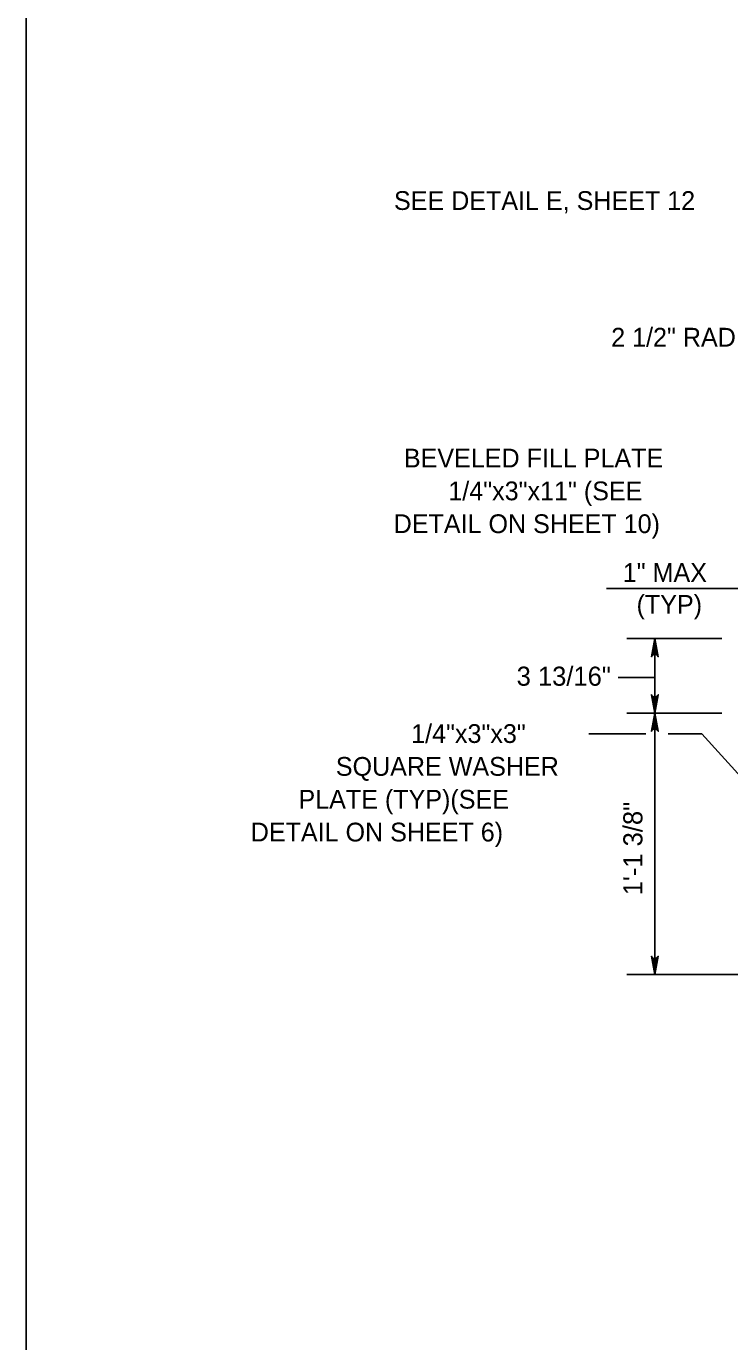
# Model space of a CAD drawing. Extents: x 632007860 to 635435983, y 295418622 to 297794622.
# Drawn here: x 634570860 to 634685141, y 297463893 to 297677572 of the extents above; entities that cross this region are included whole.
import ezdxf

# ---------------------------------------------------------------- set-up
doc = ezdxf.new("R2010")
doc.units = 0
for name, color, linetype in [('1', 7, 'Continuous'), ('S-DETL-DIMS', 7, 'Continuous'), ('S-DETL-T120', 7, 'Continuous')]:
    doc.layers.add(name, color=color, linetype=linetype)

msp = doc.modelspace()

# ---------------------------------------------------------------- linework, layer by layer
at = {"layer": '1'}
msp.add_line((634570860, 297215622), (634570860, 297779622), dxfattribs=at)
at = {"layer": 'S-DETL-DIMS'}
for p, q in [((634665111, 297586247), (634696849, 297586247)), ((634668443, 297578118), (634683847, 297578118)), ((634672972, 297578118), (634672972, 297523552)), ((634672972, 297571814), (634667041, 297571814)), ((634668443, 297566018), (634683847, 297566018)), ((634662269, 297562622), (634671501, 297562622)), ((634675127, 297562622), (634680614, 297562622)), ((634680614, 297562622), (634687563, 297555006)), ((634668443, 297523552), (634745434, 297523552))]:
    msp.add_line(p, q, dxfattribs=at)
for points in [[(634672972, 297578118), (634673527, 297575158), (634673448, 297575272), (634673369, 297575386), (634673270, 297575445), (634673171, 297575504), (634673071, 297575521), (634672972, 297575538), (634672873, 297575521), (634672774, 297575504), (634672675, 297575445), (634672575, 297575386), (634672496, 297575272), (634672417, 297575158), (634672972, 297578118), (634672496, 297575272), (634672575, 297575386), (634672972, 297578118), (634672675, 297575445), (634672774, 297575504), (634672972, 297578118), (634672873, 297575521), (634672972, 297575538), (634672972, 297578118), (634673071, 297575521), (634673171, 297575504), (634672972, 297578118), (634673270, 297575445), (634673369, 297575386), (634672972, 297578118), (634673448, 297575272)], [(634672972, 297566018), (634673527, 297568978), (634673448, 297568863), (634673369, 297568749), (634673270, 297568691), (634673171, 297568632), (634673071, 297568615), (634672972, 297568598), (634672873, 297568615), (634672774, 297568632), (634672675, 297568691), (634672575, 297568749), (634672496, 297568863), (634672417, 297568978), (634672972, 297566018), (634672496, 297568863), (634672575, 297568749), (634672972, 297566018), (634672675, 297568691), (634672774, 297568632), (634672972, 297566018), (634672873, 297568615), (634672972, 297568598), (634672972, 297566018), (634673071, 297568615), (634673171, 297568632), (634672972, 297566018), (634673270, 297568691), (634673369, 297568749), (634672972, 297566018), (634673448, 297568863)], [(634672972, 297566018), (634673527, 297563059), (634673448, 297563173), (634673369, 297563287), (634673270, 297563346), (634673171, 297563404), (634673071, 297563421), (634672972, 297563438), (634672873, 297563421), (634672774, 297563404), (634672675, 297563346), (634672575, 297563287), (634672496, 297563173), (634672417, 297563059), (634672972, 297566018), (634672496, 297563173), (634672575, 297563287), (634672972, 297566018), (634672675, 297563346), (634672774, 297563404), (634672972, 297566018), (634672873, 297563421), (634672972, 297563438), (634672972, 297566018), (634673071, 297563421), (634673171, 297563404), (634672972, 297566018), (634673270, 297563346), (634673369, 297563287), (634672972, 297566018), (634673448, 297563173)], [(634672972, 297523552), (634672417, 297526511), (634672496, 297526397), (634672575, 297526283), (634672675, 297526224), (634672774, 297526165), (634672873, 297526148), (634672972, 297526131), (634673071, 297526148), (634673171, 297526165), (634673270, 297526224), (634673369, 297526283), (634673448, 297526397), (634673527, 297526511), (634672972, 297523552), (634673448, 297526397), (634673369, 297526283), (634672972, 297523552), (634673270, 297526224), (634673171, 297526165), (634672972, 297523552), (634673071, 297526148), (634672972, 297526131), (634672972, 297523552), (634672873, 297526148), (634672774, 297526165), (634672972, 297523552), (634672675, 297526224), (634672575, 297526283), (634672972, 297523552), (634672496, 297526397)]]:
    msp.add_lwpolyline(points, dxfattribs=at)

# ---------------------------------------------------------------- texts
at = {"layer": 'S-DETL-T120'}
for s, height, p in [('SEE DETAIL E, SHEET 12', 3048.01, (634630598, 297647742)), ('2 1/2" RADIUS', 3048.01, (634665890, 297625543)), ('BEVELED FILL PLATE', 3048.01, (634632203, 297605913)), (' 1/4"x3"x11" (SEE', 3048.01, (634638299, 297600579)), ('DETAIL ON SHEET 10)', 3048.01, (634630548, 297595245)), ('1" MAX', 3048.1, (634667767, 297587314)), ('(TYP)', 3048.1, (634670011, 297582132)), ('3 13/16"', 3102.3, (634650527, 297570450)), ('1/4"x3"x3"', 3048, (634633390, 297561157)), ('SQUARE WASHER', 3048.01, (634621150, 297555823)), ('PLATE (TYP)(SEE', 3048.01, (634615078, 297550489)), ('DETAIL ON SHEET 6)', 3048.01, (634607327, 297545155))]:
    msp.add_text(s, height=height, dxfattribs=at).set_placement(p)
msp.add_text('1\'-1 3/8"', height=3102.3, rotation=90, dxfattribs=at).set_placement((634670961, 297536415))

doc.saveas('drawing.dxf')
